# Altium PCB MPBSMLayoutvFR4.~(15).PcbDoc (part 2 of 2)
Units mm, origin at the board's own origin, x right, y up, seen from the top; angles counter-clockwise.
Board outline 131.7 x 110.39 mm, 4 copper layers (Top Layer, Power, GroundPlane, Bottom Layer), stack 2.286 mm thick; 156 components, 77 nets, 429 pads, 117 vias.
Unrouted connection lines stored in the file: 44.
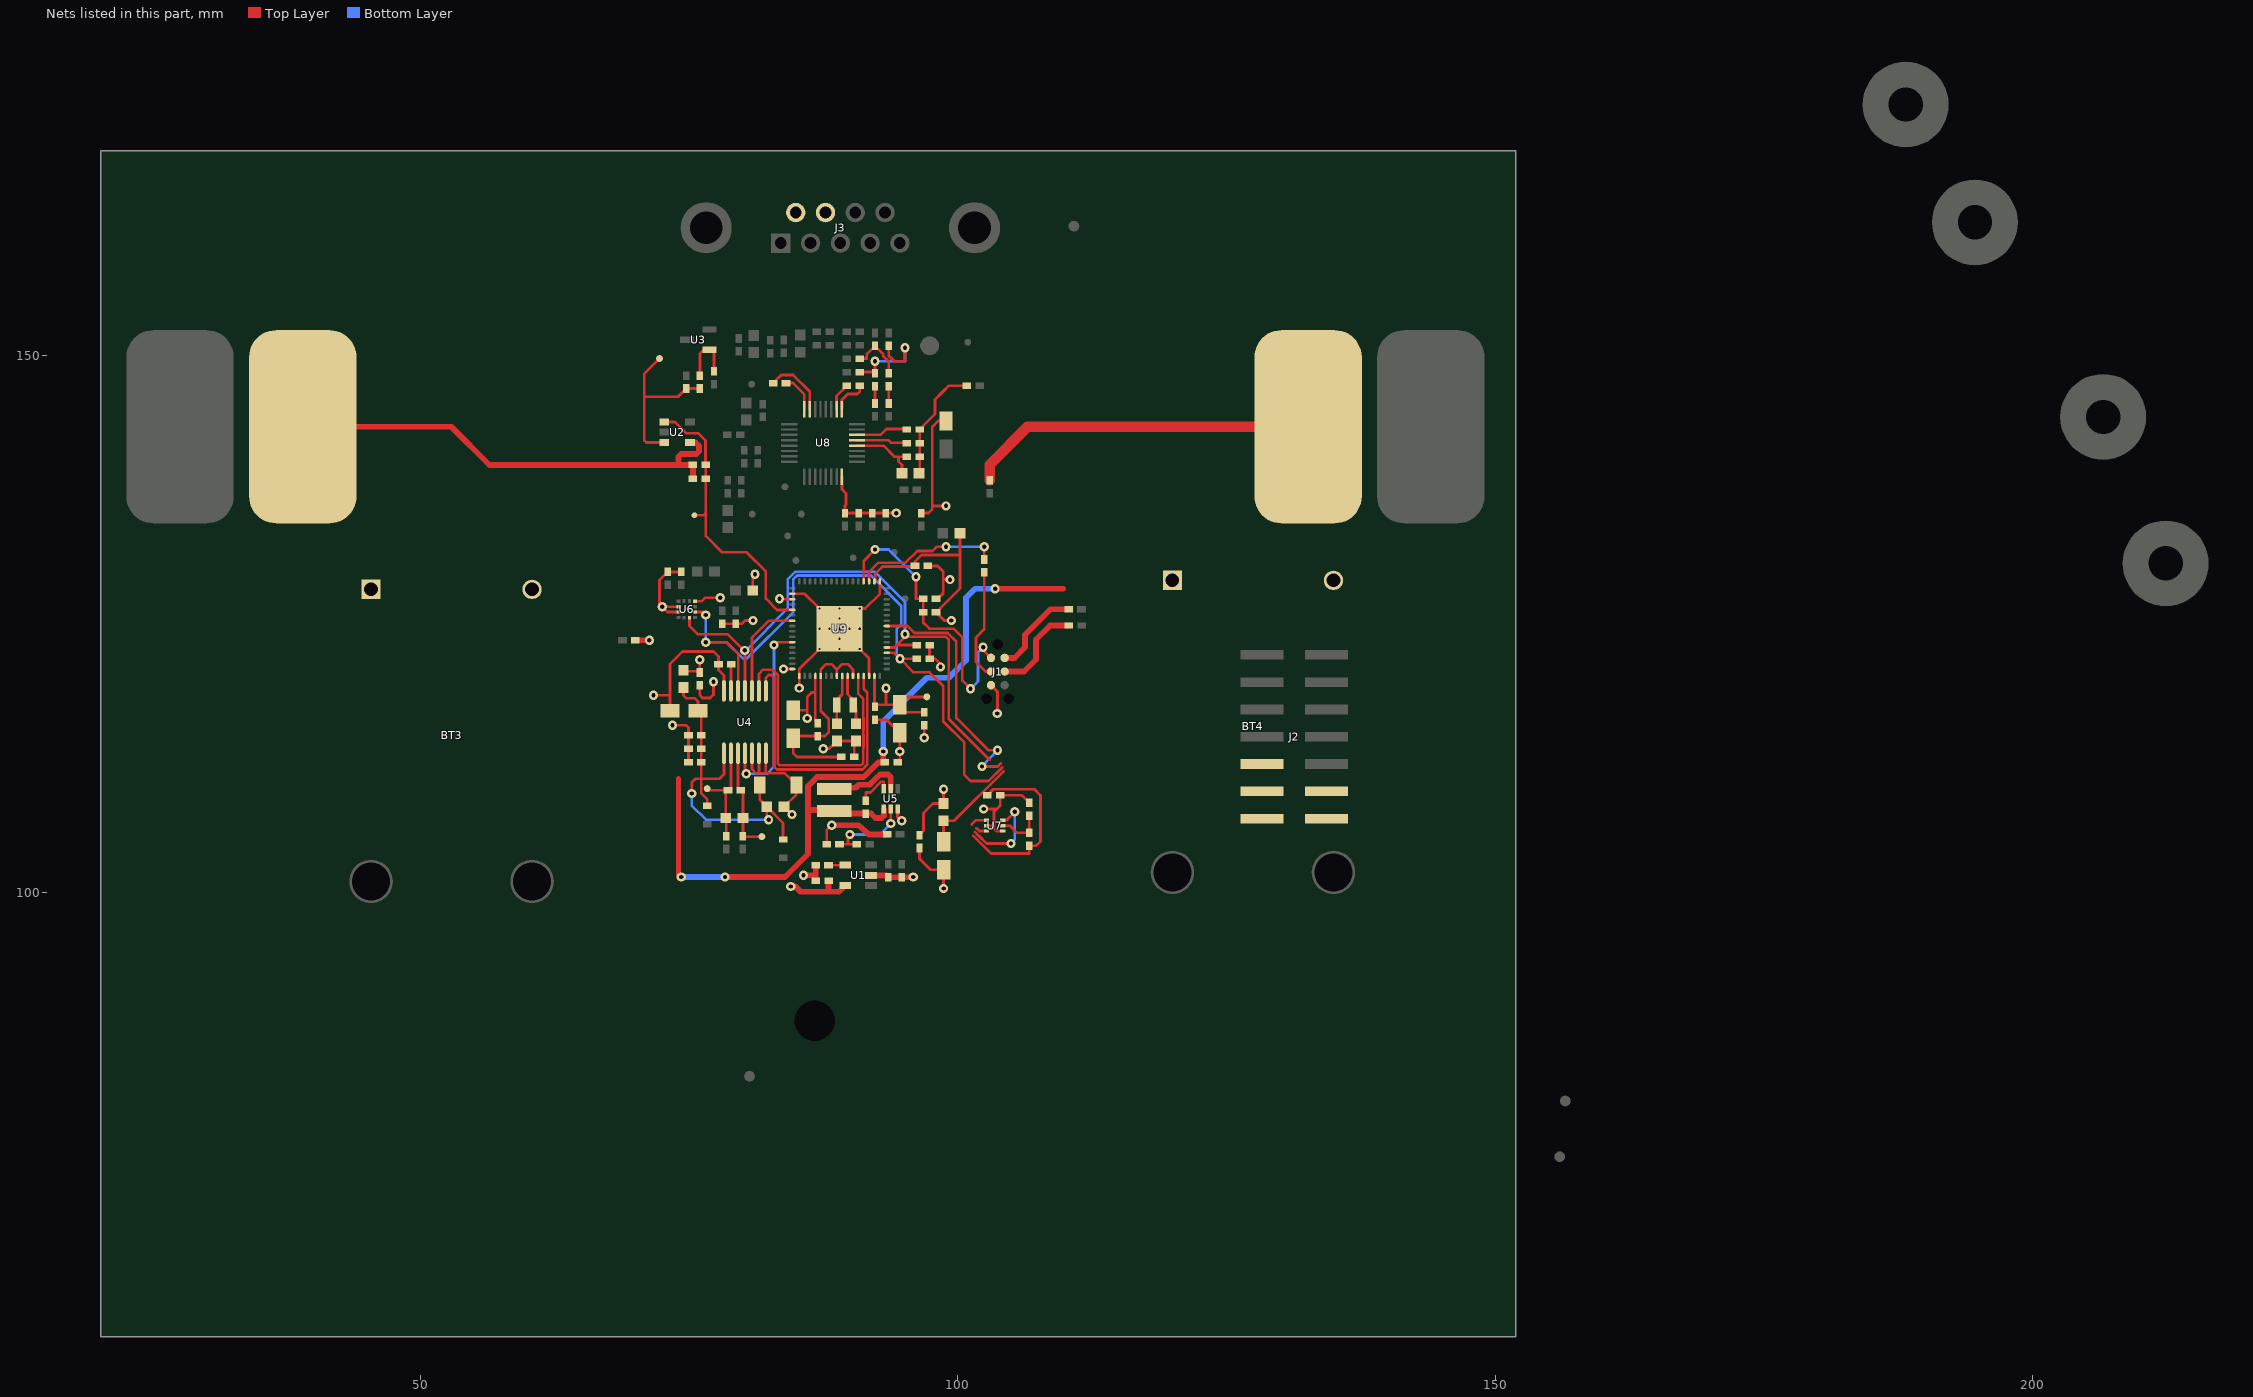
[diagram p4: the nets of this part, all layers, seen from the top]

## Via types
v1: diameter 0.864, hole 0.406, Top Layer to Bottom Layer, 104 vias
v2: diameter 0.5, hole 0.2, Top Layer to Bottom Layer, 13 vias

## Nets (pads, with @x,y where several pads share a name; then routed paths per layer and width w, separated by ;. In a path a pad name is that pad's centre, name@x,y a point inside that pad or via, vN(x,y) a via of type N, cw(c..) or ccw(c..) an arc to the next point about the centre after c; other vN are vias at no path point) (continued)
BOOST_INPUT: BT3.1 BT4.1 C34.1 L7.1 R16.1 U5.1 | length 73.3
  Top Layer w0.254: L7.1@88.494,107.681 L7.1@88.503,107.672 ; v1(93.04,113.132) v1@93.202,112.97
  Top Layer w0.5: 73.99,110.592 73.99,101.702 v1(74.244,101.448)
  Top Layer w0.54: v1(78.308,101.448) 83.896,101.448 86.03,103.581 86.03,109.906 86.868,110.744 91.211,110.744 92.583,112.116 C34.1@93.202,112.116 ; 86.03,107.696 L7.1@88.494,107.681 ; L7.1@88.714,107.35 R16.1@91.415,107.35 91.9,107.35 92.316,106.934 92.888,106.934 93.101,107.148 U5.1@93.101,107.762 ; C34.1@93.04,112.278 v1(93.04,113.132) ; v1(103.454,128.287) 109.803,128.287
  Bottom Layer w0.54: v1(74.244,101.448) v1(78.308,101.448) ; v1(93.04,113.132) 93.04,115.926 97.104,119.99 99.136,119.99 100.753,121.606 100.753,127.448 101.592,128.287 v1(103.454,128.287)
DVCC: 1.1 C1.1 C5.1 C6.1 C10.1 C14.1 C18.1 L1.1 L2.1 L3.1 L5.1 R1.1 R6.2 R31.1 R32.1 U1.5 U9.18 U9.35 U9.48 U9.63 | length 53
  Top Layer w0.254: L1.1@74.244,120.59 75.822,120.59 C10.1@75.846,120.613 ; C10.1@75.971,120.488 v1(75.971,121.666) ; L3.1@80.886,128.118 80.886,129.426 v1(81.102,129.642) ; v1@83.432,127.312 U9.35@84.576,127.312 ; v1(83.758,120.812) U9.48@84.576,120.812 ; U9.63@92.227,120.162 92.227,117.339 C6.1@92.278,117.288 ; U9.18@92.227,128.962 92.273,129.008 92.273,129.637 92.992,130.356 95.948,130.356 C18.1@95.996,130.404 95.996,130.82 96.596,131.42 100.152,131.42 ; C6.1@92.47,117.48 C1.1@94.564,117.48 ; 93.297,117.483 v1(93.297,119.027) ; C14.1@96.421,105.35 96.799,105.728 96.799,107.414 97.671,108.286 L2.1@98.661,108.286 v1(98.661,109.621) ; R1.1@96.85,116.78 95.264,116.78 C1.1@94.564,117.48 ; 1.1@97.104,118.212 95.296,118.212 C1.1@94.564,117.48 ; R32.1@97.358,123.038 R31.1@97.358,121.768 97.866,121.768 98.374,121.26 v1(98.374,121.006) ; v1(99.39,125.324) 98.72,125.324 R6.2@97.958,126.086 100.19,128.318 L5.1@100.19,133.452
  Top Layer w0.54: v1(84.43,100.559) v1@84.836,100.559 ; 84.861,100.584 85.369,100.076 87.955,100.076 ; C5.1@87.955,101.092 87.955,100.076 ; U1.5@89.503,100.65 88.929,100.076 87.955,100.076
  other v1: 83.388,127.356
EL_GSR1: C26.2 J3.7 R10.1 TP2.1 U2.4 | length 43.3
  Top Layer w0.254: U2.4@75.052,141.9 75.564,141.9
  Top Layer w0.54: TP2.1@39.014,143.358 52.832,143.358 56.388,139.802 R10.1@75.33,139.802 C26.2@75.33,138.532 ; 73.99,139.852 73.99,140.564 74.244,140.818 75.63,140.818 75.884,141.072 75.884,141.58 75.564,141.9
EL_GSR2: J3.6 R9.2 TP1.1 | length 32.6
  Top Layer w1: R9.2@102.946,138.37 102.946,139.827 106.477,143.358 TP1.1@132.588,143.358
GND: BT3.2 BT4.2 C1.2 C3.2 C4.2 C5.2 C6.2 C8.2 C9.2 C10.2 C11.2 C12.2 C13.2 C14.2 C15.2 C16.2 C17.2 C18.2 C19.2 C20.2 C21.2 C25.2 C27.2 C28.2 C29.1 C32.2 C33.2 C34.2 C35.2 C36.2 C37.2 C38.2 C41.2 C42.2 C58.2 C59.2 J1.6 J2.6 R2.1 R3.1 R17.1 U1.2 U4.5 U4.6 U4.7 U4.14 U5.3 U6.4 U6.8 U6.9 U7.2 U7.4 U8.24 U9.17 U9.34 U9.49 U9.62 U9.65 | length 145.9
  Top Layer w0.254: v1(71.653,118.364) 73.198,118.364 ; C9.2@73.198,116.942 73.198,118.364 ; v1(73.431,115.57) 74.701,115.57 74.914,115.357 C27.2@74.914,114.656 C11.2@74.914,113.386 C28.2@74.914,112.116 ; U6.9@73.977,126.111 72.949,126.111 v1(72.466,126.594) ; U6.8@73.977,126.611 72.483,126.611 v1(72.466,126.594) ; C37.2@74.244,129.847 C16.2@72.974,129.847 72.212,129.085 72.212,126.848 v1(72.466,126.594) ; U6.4@75.527,127.111 76.131,127.111 76.453,127.433 v1(77.873,127.433) ; C10.2@75.971,119.288 75.971,118.364 76.225,118.11 76.93,118.11 77.241,118.422 v1(77.241,119.634) ; C36.2@78.054,125.024 C17.2@79.324,125.024 79.88,125.024 80.18,125.324 v1(80.924,125.324) ; U4.14@78.219,118.764 78.219,120.193 77.708,120.704 C29.1@77.708,121.26 77.708,121.961 77.241,122.428 74.367,122.428 73.198,121.26 73.198,118.364 ; U4.5@80.819,112.964 80.819,111.484 81.204,111.1 82.118,111.1 ; 81.469,111.137 U4.6@81.469,112.964 ; U4.7@82.119,112.964 82.118,111.1 ; v1(84.553,107.266) 84.528,107.266 C33.2@83.803,107.991 84.957,109.145 C32.2@84.957,110.023 83.88,111.1 82.118,111.1 ; U9.34@84.576,127.812 85.726,127.812 v2(87.101,126.437) v2(88.976,124.562) ; v1(85.225,119.033) U9.49@85.225,120.162 85.225,120.811 v2(87.101,122.687) v2(88.976,124.562) ; v1(85.623,101.6) v1@85.636,101.613 ; v1(87.452,113.386) 87.998,113.386 88.722,114.11 C58.2@90.5,114.11 ; R17.1@87.776,104.496 87.776,105.812 v1(88.238,106.274) ; U8.24@89.202,138.704 89.202,137.544 89.584,137.162 89.584,136.099 89.484,135.999 C42.2@89.484,135.322 C41.2@90.754,135.322 C19.2@92.024,135.322 C20.2@93.294,135.322 v1@94.199,135.322 ; R2.1@90.338,112.624 C58.2@90.338,113.948 ; U9.62@91.727,120.162 91.727,121.811 v2(90.851,122.687) v2(88.976,124.562) ; C6.2@92.278,115.888 C6.2@92.278,116.088 93.356,116.088 C1.2@94.564,114.88 94.583,114.861 v1(94.583,113.132) 94.583,112.296 C34.2@94.402,112.116 C34.2@94.564,111.954 ; U9.17@92.727,128.962 92.727,127.805 91.359,126.437 v2(90.851,126.437) v2(88.976,124.562) ; C3.2@93.33,101.6 C3.2@93.502,101.428 ; v1(95.834,101.448) 95.834,101.194 v1@96.068,101.428 ; C14.2@96.421,104.15 96.421,103.147 97.446,102.122 C12.2@98.661,102.122 v1(98.661,100.374) ; C21.2@96.596,135.322 97.247,135.322 97.612,135.687 97.612,143.358 98.15,143.896 C15.2@98.882,143.896 C15.2@98.882,144.374 ; C18.2@97.196,130.404 98.12,130.404 98.628,129.896 98.628,129.134 ; 97.612,135.992 v1(98.882,135.992) ; C25.2@97.958,127.356 98.12,127.356 98.628,127.864 98.628,129.134 ; v1(99.263,129.134) 98.628,129.134 ; v1(102.383,107.783) 103.627,107.783 ; U7.2@102.661,106.221 103.331,106.221 ; J1.6@103.073,119.304 103.683,118.694 103.683,116.688 v1(103.657,116.662) ; U7.4@104.161,105.721 103.607,105.721 103.357,105.971 103.357,107.512 103.627,107.783 ; C38.2@106.639,108.352 105.923,109.068 C13.2@103.937,109.068 103.937,108.093 103.627,107.783
  Top Layer w0.354: U5.3@94.401,107.762 94.401,107.046 v1(94.767,106.68)
  Top Layer w0.54: R3.1@69.977,123.489 v1(71.279,123.489) ; v1@85.636,101.613 86.755,101.613 ; C5.2@86.755,101.092 86.755,101.613 ; C8.2@86.755,102.54 86.755,101.613 ; v1(88.238,106.274) 89.554,106.274 90.754,106.274 91.719,105.41 C35.2@93.455,105.41 ; U1.2@91.903,101.6 C3.2@93.33,101.6 ; C3.2@93.502,101.428 C4.2@94.772,101.428 v1@96.068,101.428
  other v1: 94.259,135.322
  other v2: 88.976,122.687 88.976,123.624 87.101,124.562 88.039,124.562 89.914,124.562 90.851,124.562 88.976,125.499 88.976,126.437
GSR_ANALOG_OUTPUT: 2.1 C26.1 R10.2 U2.1 U9.37 | length 26.9
  Top Layer w0.254: U2.1@72.652,143.8 73.659,143.8 74.71,142.748 75.828,142.748 76.488,142.088 76.488,140.14 76.53,140.098 R10.2@76.53,139.802 C26.1@76.53,138.532 76.53,135.23 ; 2.1@75.463,135.128 76.429,135.128 ; 76.429,135.23 76.53,135.23 ; U9.37@84.576,126.312 83.162,126.312 82.118,127.356 82.118,129.896 80.34,131.674 78.054,131.674 76.53,133.198 76.53,135.23
JTAG_TCK: J1.4 J2.4 R7.1 | length 10.4
  Top Layer w0.254: R7.1@102.438,129.804 102.438,124.511 101.676,123.749 101.676,121.463 102.565,120.574 J1.4@103.073,120.574
JTAG_TDO/TDI: C25.1 J1.2 J2.2 R6.1 U9.20 | length 28.1
  Top Layer w0.254: U9.20@91.227,128.962 91.227,130.876 v1(92.278,131.928) ; v1(96.088,129.388) 96.088,127.356 C25.1@96.758,127.356 R6.1@96.758,126.086 96.758,125.162 97.358,124.562 99.585,124.562 100.406,123.74 100.406,119.736 v1(101.168,118.974) ; v1(102.337,122.843) 102.337,122.58 J1.2@103.073,121.844
  Bottom Layer w0.254: v1(92.278,131.928) 93.548,131.928 v1(96.088,129.388) ; v1(101.168,118.974) 101.854,119.659 101.854,122.36 v1(102.337,122.843)
JTAG_TEST/SBWTCK: R7.2 U9.19 | length 13.7
  Top Layer w0.254: U9.19@91.727,128.962 91.727,129.852 92.584,130.71 95.124,130.71 96.215,131.801 97.611,131.801 97.992,132.182 v1(98.882,132.182) ; R7.2@102.438,131.004 v1(102.438,132.182)
  Bottom Layer w0.254: v1(98.882,132.182) v1(102.438,132.182)
JTAG_VCC_TARGET_IN: J1.3 J2.3 R5.1 | length 8.8
  Top Layer w0.54: J1.3@104.343,120.574 106.147,120.574 107.264,121.691 107.264,122.707 107.264,123.546 108.58,124.861 R5.1@110.316,124.861
JTAG_VCC_TOOL_OUT: J1.1 J2.1 R4.1 | length 8.5
  Top Layer w0.54: J1.1@104.343,121.844 105.258,121.844 106.248,122.834 106.248,124.003 108.61,126.365 R4.1@110.296,126.365
MSP_AVCC: C2.1 C7.1 R1.2 U9.52 | length 9.3
  Top Layer w0.254: C2.1@84.978,116.972 85.958,116.972 ; v1(85.958,116.21) 85.958,116.972 ; C7.1@86.726,115.982 86.726,118.618 ; U9.52@86.726,120.162 86.726,118.618 ; v1(96.85,114.402) R1.2@96.85,115.58 ; 85.958,116.972 85.958,118.191 86.385,118.618 86.726,118.618
MSP_AVSS: C2.2 C7.2 R2.2 U9.53 U9.56 U9.59 | length 20.5
  Top Layer w0.254: C2.2@84.658,114.372 84.658,112.979 85.014,112.624 R2.2@89.138,112.624 ; C2.2@84.85,114.564 C7.2@86.944,114.564 87.614,114.564 87.96,114.91 87.96,116.18 87.226,116.914 U9.53@87.226,120.162 87.226,120.779 87.706,121.26 88.214,121.26 88.718,120.756 ; U9.56@88.726,120.162 88.726,120.756 89.23,121.26 89.738,121.26 90.227,120.771 U9.59@90.227,120.162
MSP_LFXIN: C59.1 U9.57 Y1.1 | length 4.1
  Top Layer w0.254: C59.1@88.722,115.71 88.722,117.438 Y1.1@88.734,117.45 ; Y1.1@88.734,117.97 89.226,118.462 U9.57@89.226,120.162
MSP_LFXOUT: C58.1 U9.58 Y1.2 | length 4.3
  Top Layer w0.254: U9.58@89.726,120.162 89.726,118.477 Y1.2@90.234,117.97 ; Y1.2@90.234,117.45 90.5,117.184 C58.1@90.5,115.71
MSP_P1.0_INT: U4.10 U9.39 | length 9.4
  Top Layer w0.254: U4.10@80.819,118.764 80.819,123.749 ; 80.835,123.749 82.398,125.312 U9.39@84.576,125.312
MSP_P2.7_INT: U7.3 U9.9 | length 24.2
  Top Layer w0.254: U9.9@93.376,124.812 95.3,124.812 95.958,124.154 99.036,124.154 99.844,123.346 99.844,116.234 102.819,113.259 v1(103.683,113.259) ; 101.723,105.989 101.992,105.721 U7.3@102.661,105.721 ; v1@102.243,111.743 103.704,111.743 103.972,112.011
  Bottom Layer w0.254: v1(102.235,111.735) v1(103.683,113.259)
MSP_P4.0_INT: U4.9 U9.60 | length 28.4
  Top Layer w0.254: U4.9@81.469,118.764 81.469,120.356 81.864,120.752 82.731,120.752 83.234,120.248 83.234,112.016 83.388,111.862 91.008,111.862 91.193,112.046 91.193,113.506 91.202,113.516 91.202,114.704 91.193,114.713 91.193,115.106 91.202,115.116 91.202,116.304 91.193,116.313 91.193,118.027 90.727,118.493 U9.60@90.727,120.162
MSP_P4.1_INT: U4.8 U9.61 | length 27.8
  Top Layer w0.254: U4.8@82.119,118.764 82.119,119.99 82.372,120.244 82.626,120.244 82.88,119.99 82.88,111.718 83.144,111.454 91.108,111.454 ; 91.108,111.461 91.547,111.9 91.547,113.36 91.556,113.369 91.556,118.612 91.227,118.942 U9.61@91.227,120.162
MSP_P9.3_OUT: U4.4 U9.43 | length 18
  Top Layer w0.254: U4.4@80.169,112.964 80.169,111.169 v1(80.289,111.049) ; v1(82.88,123.038) 83.154,123.312 U9.43@84.576,123.312
  Bottom Layer w0.254: v1(80.289,111.049) 82.211,111.049 82.88,111.718 v1(82.88,123.038)
MSP_UCB0SCL_TMP103_SCL_RF430CL330HCPW_SCL: R32.2 U4.11 U6.12 U7.1 U9.5 | length 56.8
  Top Layer w0.254: U6.12@75.002,125.586 75.002,124.82 75.768,124.054 78.562,124.054 v1@80.118,122.497 ; U4.11@80.169,118.764 v1@80.169,122.447 ; U9.5@93.376,122.812 94.084,122.812 94.31,123.038 ; v1(95.072,124.054) v1@95.072,123.8 ; R32.2@95.996,123.038 94.31,123.038 ; 101.273,106.343 101.651,106.721 U7.1@102.661,106.721 ; 102.926,112.365 102.744,112.547 99.136,116.18 99.136,123.546 98.882,123.8 v1@95.072,123.8 ; 94.31,123.038 v1@95.072,123.8
  Bottom Layer w0.254: v1(80.16,122.539) 80.169,122.531 80.169,122.447 84.15,126.428 84.15,129.134 84.883,129.866 92.248,129.866 95.072,127.042 v1(95.072,124.054)
MSP_UCB0SDA_TMP103_SDA_RF430CL330HCPW_SDA: R31.2 U4.12 U6.2 U7.6 U9.4 | length 70.6
  Top Layer w0.254: U6.2@75.527,126.111 76.251,126.111 v1(76.53,125.832) ; v1(76.53,123.292) 78.476,123.292 79.535,122.233 79.535,118.78 U4.12@79.519,118.764 ; U9.4@93.376,122.312 94.056,122.312 v1(94.6,121.768) ; R31.2@96.158,121.768 v1(94.6,121.768) ; 101.577,105.635 101.88,105.332 101.887,105.332 102.649,104.57 v1(104.935,104.57) ; 104.119,111.657 102.85,110.388 101.168,110.388 100.597,110.96 100.597,113.957 98.628,115.926 98.628,119.228 97.358,120.498 95.87,120.498 v1(94.6,121.768) ; U7.6@104.161,106.721 104.496,106.721 v1(105.291,107.516)
  Bottom Layer w0.254: v1(76.53,125.832) v1(76.53,123.292) 78.476,123.292 80,121.768 80.34,121.768 84.658,126.086 84.658,129.134 85.037,129.512 91.9,129.512 94.718,126.694 94.718,124.97 94.31,124.562 94.31,122.058 v1(94.6,121.768) ; v1(104.935,104.57) 105.291,104.925 v1(105.291,107.516)
Net3_1: 3.1 R11.1 R12.2 U2.3 | length 15.6
  Top Layer w0.254: 70.804,146.152 73.941,146.152 R12.2@74.707,146.917 R11.1@75.977,146.917 ; 3.1@72.212,149.708 70.804,148.3 70.804,142.088 70.992,141.9 U2.3@72.652,141.9
Net4_1: 4.1 C30.1 C31.1 R13.1 U4.2 | length 9.9
  Top Layer w0.254: 4.1@76.653,109.676 76.814,109.515 C31.1@78.593,109.515 ; R13.1@78.431,105.255 78.431,106.903 C30.1@78.393,106.941 78.393,109.315 C31.1@78.593,109.515 ; U4.2@78.869,112.964 78.869,109.791 C31.1@78.593,109.515
Net5_1: 5.1 C30.2 C31.2 R14.1 U4.3 | length 9.9
  Top Layer w0.254: U4.3@79.519,112.964 79.519,109.788 C31.2@79.793,109.515 79.993,109.315 C30.2@79.993,106.941 79.993,105.293 80.089,105.197 5.1@81.987,105.197
NetC8_1: C8.1 U1.4 | length 1.6
  Top Layer w0.254: C8.1@87.951,102.54 87.961,102.55 U1.4@89.503,102.55
NetC29_2: C29.2 U4.13 | length 2.5
  Top Layer w0.254: U4.13@78.869,118.764 78.869,121.22 C29.2@78.908,121.26
NetC38_1: C38.1 R18.1 U7.5 | length 4.3
  Top Layer w0.254: U7.5@104.161,106.221 104.834,106.221 105.497,105.558 R18.1@106.639,105.558 C38.1@106.639,107.152
NetC43_1: C43.1 R19.2 R20.2 R21.2 R22.1 | length 10.9
  Top Layer w0.254: C43.1@96.434,139.094 R20.2@96.434,140.564 R21.2@96.434,141.834 96.434,141.876 R19.2@96.434,143.104 97.866,144.536 97.866,145.898 98.586,146.618 99.136,147.168 R22.1@100.822,147.168
NetC43_2: C43.2 R20.1 U8.28 | length 6.7
  Top Layer w0.254: U8.28@90.602,141.603 93.055,141.603 94.094,140.564 94.463,140.564 ; C43.2@94.78,139.04 94.78,139.818 94.463,140.135 94.463,140.564 ; R20.1@95.234,140.564 94.463,140.564
NetC45_1: C45.1 U8.2 | length 2.6
  Top Layer w0.254: U8.2@88.702,145.003 88.702,146.224 C45.1@89.646,147.168
NetC45_2: C45.2 U8.1 | length 3.4
  Top Layer w0.254: U8.1@89.202,145.003 89.202,145.87 89.738,146.406 90.64,146.406 90.846,146.612 C45.2@90.846,147.168
NetC46_2: C46.2 C48.2 C49.2 | length 10.4
  Top Layer w0.254: C46.2@90.846,148.45 C49.2@92.149,148.45 ; C49.2@92.278,148.322 v1(92.278,149.454) ; C48.2@93.548,150.886 93.554,150.88 93.554,149.967 94.068,149.454 95.072,149.454 v1(95.072,150.724)
  Bottom Layer w0.254: v1(92.278,149.454) 95.072,149.454 v1(95.072,150.724)
NetC47_1: C47.1 U8.8 | length 3.5
  Top Layer w0.254: C47.1@83.988,147.422 84.658,147.422 85.702,146.378 U8.8@85.702,145.003
NetC47_2: C47.2 U8.7 | length 6
  Top Layer w0.254: C47.2@82.788,147.422 83.55,148.184 84.658,148.184 86.202,146.64 U8.7@86.202,145.003
NetC49_1: C49.1 R26.1 | length 1.6
  Top Layer w0.254: R26.1@92.278,145.528 C49.1@92.278,147.122
NetC52_2: C52.2 C53.2 C54.2 | length 5.3
  Top Layer w0.254: C54.2@90.846,149.708 91.516,149.708 91.516,150.124 C52.2@92.278,150.886 93.04,150.124 93.04,149.962 93.548,149.454 C53.2@93.548,148.322
NetC53_1: C53.1 R27.1 | length 1.6
  Top Layer w0.254: R27.1@93.548,145.528 C53.1@93.548,147.122
NetL7_2: L7.2 U5.5 | length 5.5
  Top Layer w0.254: 91.821,110.033 91.821,110.084
  Top Layer w0.54: L7.2@89.941,109.752 90.473,109.752 90.754,110.033 91.821,110.033 ; 91.821,110.084 92.401,110.664 92.735,110.998 93.497,110.998 93.751,110.744 U5.5@93.751,109.662
NetR8_1: R8.1 R11.2 U3.1 | length 5.5
  Top Layer w0.254: R11.2@75.977,148.117 75.977,150.17 76.342,150.536 77.292,150.536 R8.1@77.292,148.53
NetR15_1: R15.1 R17.2 U5.2 | length 8.1
  Top Layer w0.254: R17.2@88.976,104.496 89.773,104.496 ; v1(89.941,105.41) 89.773,105.242 89.773,104.496 ; R15.1@90.57,104.496 89.773,104.496 ; v1(93.751,106.426) U5.2@93.751,107.762
  Bottom Layer w0.254: v1(89.941,105.41) 92.735,105.41 v1(93.751,106.426)
NetR16_2: R16.2 U5.6 | length 3.5
  Top Layer w0.254: R16.2@91.415,108.55 91.415,109.271 91.465,109.322 91.846,109.322 92.851,110.327 93.091,110.327 93.091,109.672 U5.6@93.101,109.662
NetR19_1: R19.1 U8.30 | length 4.9
  Top Layer w0.254: U8.30@90.602,142.603 92.794,142.603 93.336,143.146 R19.1@95.234,143.146
NetR21_1: R21.1 U8.29 | length 4.7
  Top Layer w0.254: U8.29@90.602,142.103 93.533,142.103 93.76,141.876 R21.1@95.234,141.876
RF430_DVCC: C9.1 C11.1 C27.1 C28.1 C32.1 C33.1 D1.1 D2.1 L1.2 U4.1 | length 34
  Top Layer w0.254: 74.447,118.512 74.447,118.338 74.694,118.092 75.482,118.092 75.798,117.775 C9.1@75.798,116.942 C9.1@76.022,117.166 ; v1(75.209,109.22) 75.209,110.236 75.565,110.592 76.108,110.592 ; C28.1@76.114,112.116 C11.1@76.114,113.386 C27.1@76.114,114.656 C9.1@76.114,116.626 ; C28.1@76.206,112.024 76.108,111.926 76.108,110.592 ; D1.1@76.653,108.079 76.653,108.691 76.108,109.235 76.108,110.592 ; U4.1@78.219,112.964 78.219,111.01 77.8,110.592 76.108,110.592 ; C32.1@81.557,110.023 81.557,108.637 C33.1@82.203,107.991 ; v1(82.372,106.782) 82.203,106.951 C33.1@82.203,107.991 ; D2.1@83.718,104.989 83.718,106.475 C33.1@82.203,107.991
  Bottom Layer w0.254: v1(75.209,109.22) 75.209,108.102 76.53,106.782 v1(82.372,106.782)
TMP_DVCC: C12.1 C13.1 L2.2 R18.2 | length 27
  Top Layer w0.254: C12.1@98.661,104.722 L2.2@98.661,106.686 99.648,106.686 104.265,111.303 ; 101.43,105.281 103.081,103.63 106.639,103.63 R18.2@106.639,104.358 107.263,104.358 107.674,104.768 107.674,109.049 107.105,109.618 103.287,109.618 C13.1@102.737,109.068
pads on no net: BT3.3 BT3.4 BT4.3 BT4.4 FID1.1 FID2.1 FID3.1 H1.0 H2.0 H3.0 H4.0 H5.1 H6.1 H7.1 H8.1 H9.0 H10.0 H11.0 H12.0 J1.5 J1.MH1 J1.MH2 J1.MH3 J2.5 J2.7 J2.8 J2.9 J2.10 J2.11 J2.12 J2.13 J2.14 J3.3 J3.5 J3.8 J3.9 U3.3 U6.10 U8.17 U9.1 U9.2 U9.3 U9.6 U9.7 U9.8 U9.10 U9.11 U9.12 U9.13 U9.15 U9.21 U9.22 U9.23 U9.24 U9.36 U9.40 U9.41 U9.42 U9.44 U9.45 U9.46 U9.47 U9.50 U9.51 U9.54 U9.55 U9.64
copper on no net: | length 0.5
  Top Layer w0.254: 103.403,124.206 v1(103.403,124.714)

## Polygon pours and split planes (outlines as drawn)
DVCC on Power (split plane): 101.293,142.288 101.293,131.727 100.657,131.092 77.549,131.092 76.914,131.727 76.914,133.144 78.108,134.338 92.024,134.338 92.074,134.348 92.116,134.376 97.196,139.456 97.224,139.498 97.234,139.548 97.234,142.796 97.642,143.205 100.376,143.205
DVCC on Power (split plane): 86.469,117.065 86.815,116.61 86.815,112.624 86.825,112.574 86.853,112.532 86.895,112.504 86.944,112.494 94.91,112.494 94.96,112.504 95.002,112.532 95.926,113.456 95.954,113.498 95.964,113.548 95.964,115.796 97.727,115.796 97.727,115.57 97.727,113.937 97.267,113.477 95.989,112.2 95.527,111.737 85.686,111.737 85.042,112.41 85.042,116.653 85.456,117.089
DVCC on Power (split plane): 89.609,154.534 89.567,146.998 80.849,147.043 80.848,147.043 80.824,147.038 80.799,147.033 80.778,147.019 80.757,147.006 80.757,147.005 80.743,146.984 80.729,146.964 80.729,146.963 80.724,146.939 80.719,146.914 80.719,143.104 80.729,143.054 80.757,143.012 80.799,142.984 80.848,142.974 85.545,142.974 85.545,141.201 82.372,141.201 82.323,141.191 82.281,141.163 82.253,141.121 82.243,141.072 82.243,135.359 76.101,135.359 76.101,139.09 76.091,139.14 76.063,139.182 73.866,141.379 73.866,145.59 76.883,148.607 78.021,148.607 78.046,148.612 78.07,148.616 78.071,148.617 78.092,148.631 78.112,148.644 78.113,148.645 78.127,148.665 78.141,148.686 78.141,148.687 78.146,148.711 78.151,148.736 78.183,154.658 89.609,154.658
DVCC on Power (split plane): 151.407,158.471 151.407,59.159 20.729,59.159 20.729,168.527 151.407,168.527
ADS_AVSS on GroundPlane (split plane): 151.407,158.471 151.407,59.159 20.729,59.159 20.729,127.759 76.632,127.734 76.681,127.744 76.724,127.772 76.727,127.776 76.742,127.784 88.378,136.269 95.146,136.269 95.146,135.636 95.156,135.586 95.184,135.544 95.226,135.516 95.275,135.507 97.866,135.507 97.916,135.516 97.958,135.544 97.986,135.586 97.996,135.636 97.996,136.878 100.785,136.878 100.785,128.676 100.795,128.627 100.823,128.585 100.865,128.557 100.914,128.547 150.673,128.547 150.722,128.557 150.764,128.585 150.792,128.627 150.802,128.676 150.792,128.726 150.764,128.768 150.722,128.796 150.673,128.806 101.044,128.806 101.044,137.008 101.034,137.057 101.006,137.099 100.964,137.127 100.914,137.137 97.866,137.137 97.817,137.127 97.775,137.099 97.747,137.057 97.737,137.008 97.737,135.765 95.405,135.765 95.405,136.398 95.395,136.448 95.367,136.49 95.325,136.518 95.275,136.527 88.336,136.527 88.321,136.524 88.306,136.524 88.297,136.52 88.287,136.518 88.274,136.509 88.26,136.503 76.59,127.993 20.729,128.018 20.729,168.527 151.407,168.527

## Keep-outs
Keep-Out Layer:
  text ".Layer_Name" at 157.226,108.306 h1.52

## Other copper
Top Layer:
  text ".Layer_Name" at 157.226,156.566 h1.52
Bottom Layer:
  text ".Layer_Name" at 157.226,154.026 h1.52
  text "SVN:" at 48.603,114.91 h1.52 r90
  text ".VersionControl_RevNumber" at 48.603,107.823 h1.52 r90
  text "UL94V-0" at 54.635,69.774 h1.52 r90
Power (plane layer: these items are gaps in the copper):
  rectangle: 73.736,69.952 99.136,99.67
  lines w0.254: 97.856,115.57 97.856,115.926 ; 97.856,115.926 97.453,115.926 95.834,115.926 95.834,113.548 94.91,112.624 87.164,112.624 86.944,112.624 86.944,116.654 86.534,117.193 85.402,117.219 84.912,116.705 84.912,112.358 85.63,111.608 91.098,111.608 95.58,111.608 96.081,112.108 97.358,113.386 97.856,113.884 97.856,115.926 ; 73.736,141.326 75.971,139.09 75.971,135.23 80.144,135.23 82.372,135.23 82.372,141.072 85.674,141.072 85.674,143.104 80.848,143.104 80.848,146.914 89.696,146.868 89.738,154.534 89.738,154.788 78.054,154.788 78.021,148.736 76.829,148.736 73.736,145.644 73.736,141.326 ; 76.784,131.674 76.784,133.198 78.054,134.468 92.024,134.468 97.104,139.548 97.104,142.85 97.589,143.334 100.43,143.334 101.422,142.342 101.422,131.674 100.711,130.962 77.495,130.962 76.784,131.674
GroundPlane (plane layer: these items are gaps in the copper):
  rectangle: 73.736,69.952 99.136,99.67
  lines w0.254: 18.999,127.889 76.632,127.864 ; 76.666,127.888 88.336,136.398 95.275,136.398 95.275,135.636 97.866,135.636 97.866,137.008 100.914,137.008 100.914,128.676 150.673,128.676

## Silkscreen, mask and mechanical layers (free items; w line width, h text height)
Top Overlay:
  region: 95.275,77.724 95.275,85.344 92.735,85.344 92.735,77.724
  lines w1: 72.822,70.891 99.949,70.891 99.949,98.222 72.822,98.222 72.822,70.891
  lines w2: 19.888,133.325 43.688,133.325 149.2,133.325 ; 47.879,60.96 47.879,132.918 47.879,167.716 ; 124.587,61.646 124.587,167.157
  text "GSR" at 129.007,153.289 h4
  text "ECG" at 140.386,153.238 h4
  text "ECG" at 23.647,152.806 h4
  text "GSR" at 36.297,152.756 h4
  text "GND" at 45.542,131.318 h1.02
  text "VCC" at 59.055,129.845 h1.02
  text ".Layer_Name" at 157.226,128.626 h1.52
  text "JTAG" at 105.689,126.009 h1.02
  text "BAT" at 109.499,122.987 h1.02
  text "VCC" at 60.935,121.361 h1.02
  text "GND" at 45.796,121.158 h1.02
  text "FOR DEMO PURPOSES ONLY" at 75.438,94.259 h1.02
  text "MPBSM" at 79.019,91.44 h1.02
  text "REV A" at 79.019,89.916 h1.02
  text "TI" at 91.11,87.884 h1.52
  text "©" at 93.751,87.63 h2.67
  text ".CopyrightYear" at 84.099,77.724 h1.52
  text "MADE IN U.S." at 77.749,75.438 h1.52
  text "NFC Antenna" at 79.502,68.504 h2
  text "-" at 49.86,67.666 h1.52 r90
  text "Place phone here" at 51.867,62.84 h10
Bottom Overlay:
  text ".Layer_Name" at 157.226,126.086 h1.52
Top Paste:
  text ".Layer_Name" at 157.226,123.546 h1.52
Bottom Paste:
  text ".Layer_Name" at 157.226,121.006 h1.52
Top Solder:
  text ".Layer_Name" at 157.226,118.466 h1.52
  text ".Layer_Name" at 157.226,115.926 h1.52
Bottom Solder:
  text ".Layer_Name" at 157.226,113.386 h1.52
Drill Guide:
  text ".Layer_Name" at 157.226,110.846 h1.52
M1 Board Outline:
  lines w0.254: 74.244,58.257 100.533,58.257
  text ".Layer_Name" at 157.226,151.486 h1.52
M2 Board Dimensions:
  rectangle: 17.577,32.982 20.752,36.157
  rectangle: 20.752,29.807 30.277,32.982
  lines w0.178: 17.577,32.982 42.977,32.982 ; 20.752,29.807 20.752,36.157 ; 23.927,29.807 23.927,36.157 ; 30.277,29.807 30.277,36.157 ; 36.627,29.807 36.627,36.157 ; 17.577,29.807 42.977,29.807 42.977,36.157 17.577,36.157 17.577,29.807
  text ".Layer_Name" at 18.034,37.338 h1.52
M3 3D STEP Top:
  text ".Layer_Name" at 157.226,148.946 h1.52
M4 3D STEP Bottom:
  text ".Layer_Name" at 157.226,146.406 h1.52
M5 Assembly Top:
  lines w0.254: 10.16,16.607 177.8,16.607 ; 10.16,21.772 177.851,21.772 ; 10.16,26.937 10.16,11.443 111.887,11.443 177.851,11.443 177.851,26.937 10.173,26.937 10.173,11.443 50.19,11.443 ; 72.771,11.443 72.771,26.937 ; 104.953,21.772 104.953,26.937 ; 126.289,21.772 126.289,26.937 ; 142.088,11.278 142.088,16.43
  text "COMPONENTS MARKED 'DNP' SHOULD NOT BE POPULATED." at 46.876,32.144 h1.52
  text "ASSEMBLY VARIANT:" at 46.863,29.21 h1.52
  text ".VariantName" at 73.177,29.21 h1.52
  text "PCB VIEWED FROM TOP SIDE" at 11.773,23.58 h1.52
  text "BOARD #:" at 74.676,23.58 h1.52
  text ".PRJ_Number" at 88.532,23.58 h1.52
  text "REV:" at 109.982,23.58 h1.52
  text ".PCB_Rev" at 117.386,23.58 h1.52
  text "SVN REV:" at 131.267,23.58 h1.52
  text ".VersionControl_RevNumber" at 144.12,23.58 h1.52
  text "IGNORE ->" at 11.773,18.428 h1.52
  text "PLOT NAME =" at 11.773,13.199 h1.52
  text ".plot_File_Name" at 32.233,13.199 h1.52
  text "GENERATED    :" at 74.727,13.199 h1.52
  text ".Print_Date" at 96.812,13.199 h1.52
  text ".Print_Time" at 115.329,13.199 h1.52
  text "TEXAS INSTRUMENTS" at 147.447,13.199 h1.52
M6 Assembly Bottom:
  lines w0.254: 10.147,21.759 177.838,21.759 ; 10.198,16.595 177.838,16.595 ; 45.91,11.265 45.91,16.417 ; 61.709,21.759 61.709,26.924 ; 83.045,21.759 83.045,26.924 ; 115.227,11.43 115.227,26.924 ; 137.808,11.43 177.825,11.43 177.825,26.924 10.147,26.924 10.147,11.43 76.111,11.43 177.838,11.43 177.838,26.924
  text "COMPONENTS MARKED 'DNP' SHOULD NOT BE POPULATED." at 172.568,32.156 h1.52
  text ".VariantName" at 146.05,29.21 h1.52
  text "ASSEMBLY VARIANT:" at 172.441,29.21 h1.52
  text ".VersionControl_RevNumber" at 43.878,23.567 h1.52
  text "SVN REV:" at 56.731,23.567 h1.52
  text ".PCB_Rev" at 70.612,23.567 h1.52
  text "REV:" at 78.016,23.567 h1.52
  text ".PRJ_Number" at 99.466,23.567 h1.52
  text "BOARD #:" at 113.322,23.567 h1.52
  text "PCB VIEWED FROM BOTTOM SIDE" at 176.225,23.567 h1.52
  text "IGNORE ->" at 82.292,18.428 h1.52
  text "TEXAS INSTRUMENTS" at 40.551,13.187 h1.52
  text ".Print_Time" at 72.669,13.187 h1.52
  text ".Print_Date" at 91.186,13.187 h1.52
  text "GENERATED    :" at 113.271,13.187 h1.52
  text ".plot_File_Name" at 155.766,13.187 h1.52
  text "PLOT NAME =" at 176.225,13.187 h1.52
M9 Title Sheet:
  drawing of 57 lines, arcs and shapes, not listed
  text "1" at 36.369,243.091 h1.78
  text "2" at 99.758,243.091 h1.78
  text "3" at 162.988,243.091 h1.78
  text "4" at 226.657,243.091 h1.78
  text "5" at 290.131,243.091 h1.78
  text "6" at 353.758,243.091 h1.78
  text "A" at 6.998,214.058 h1.78
  text "A" at 382.918,214.058 h1.78
  text "B" at 6.998,153.606 h1.78
  text "B" at 382.918,153.606 h1.78
  text ".Layer_Name" at 157.226,143.866 h1.52
  text "C" at 6.998,93.281 h1.78
  text "C" at 382.918,93.281 h1.78
  text "PROJECT TITLE:" at 305.702,46.012 h1.14
  text ".PRJ_Title" at 306.972,42.626 h1.78
  text "DESIGNED FOR:" at 305.702,38.367 h1.14
  text ".PRJ_Customer" at 306.972,34.811 h1.78
  text "D" at 6.998,33.084 h1.78
  text "D" at 382.918,33.084 h1.78
  text "FILE NAME:" at 305.702,30.747 h1.14
  text ".PCB_File_Name_No_Path" at 306.972,27.699 h1.78
  text "Texas Instruments (TI) and/or its licensors do not warrant the accuracy or completeness of this specification" at 179.476,23.588 h1.14
  text "ENGINEER:" at 305.702,23.381 h1.14
  text "LAYOUT BY:" at 343.929,23.381 h1.14
  text "or any information contained therein. TI and/or its licensors do not warrant that this design will meet" at 178.334,20.726 h1.14
  text ".PRJ_Engineer" at 306.972,19.444 h1.78
  text ".PCB_Layout" at 345.211,19.444 h1.78
  text "the specifications, will be suitable for your application or fit for any particular purpose, or will operate in" at 178.334,17.865 h1.14
  text "ALTIUM DESIGNER VERSION:" at 343.929,15.507 h1.14
  text "an implementation. TI and/or its licensors do not warrant that the design is production worthy. You should" at 178.334,15.003 h1.14
  text "completely validate and test your design implementation to confirm the system functionality for your application." at 179.476,12.141 h1.14
  text ".print_Scale" at 306.972,12.12 h1.78
  text ".Application_BuildNumber" at 345.211,12.12 h1.78
  text "1" at 36.369,6.871 h1.78
  text "2" at 99.758,6.871 h1.78
  text "3" at 162.988,6.871 h1.78
  text "4" at 226.657,6.871 h1.78
  text "5" at 290.131,6.871 h1.78
  text "6" at 353.758,6.871 h1.78
M10 Fab Notes:
  drawing of 185 lines, arcs and shapes, not listed
  text "DESIGN INFORMATION" at 332.055,190.348 h1.52
  text "MIN. TRACK WIDTH:" at 315.683,185.776 h1.52
  text "8" at 343.527,185.776 h1.52
  text "MIL" at 347.458,185.776 h1.52
  text "MIN. CLEARANCE:" at 315.683,182.423 h1.52
  text "0.2" at 342.003,182.423 h1.52
  text "mm" at 347.458,182.423 h1.52
  text "MIN. VIA PAD SIZE:" at 315.683,179.07 h1.52
  text "24" at 342.766,179.07 h1.52
  text "MIL" at 347.458,179.07 h1.52
  text "0.05mm (2MIL)" at 333.336,175.471 h1.52
  text "MINIMUM ANNULAR RING" at 307.32,175.362 h1.52
  text "EXTERNAL" at 351.319,175.362 h1.52
  text "PER" at 312.4,172.364 h1.52
  text "IPC-D-275 CLASS 2 LEVEL C" at 317.988,172.364 h1.52
  text "MIL, HOLES" at 355.789,169.512 h1.52
  text "+/-" at 345.821,169.494 h1.52
  text "+/-" at 367.513,169.494 h1.52
  text "REGISTRATION TOLERANCES:" at 307.32,169.367 h1.52
  text "METAL" at 337.795,169.367 h1.52
  text "5" at 352.43,169.367 h1.52
  text "3" at 373.588,169.367 h1.52
  text "MIL" at 376.541,169.367 h1.52
  text "MATERIAL:" at 305.421,164.047 h1.52
  text "FR-4 High Tg" at 330.477,160.482 h1.52
  text "FR-408" at 316.115,160.265 h1.52
  text "X" at 326.579,160.265 h1.52
  text "OTHER" at 353.91,160.265 h1.52
  text "62 MIL (1.6mm) +/-10%" at 324.245,156.132 h1.52
  text "THICKNESS:" at 307.32,156.023 h1.52
  text "X" at 320.99,156.023 h1.52
  text "OTHER" at 356.882,156.023 h1.52
  text "TOLERANCE:" at 307.32,152.01 h1.52
  text "X" at 328.639,152.01 h1.52
  text "ANSI IPC-6012 TYPE 3 CLASS 2" at 333.387,152.01 h1.52
  text "OTHER +/-" at 333.387,148.047 h1.52
  text "BOW & TWIST:" at 307.32,144.06 h1.52
  text "X" at 328.639,144.06 h1.52
  text "ANSI IPC-6012 TYPE 3 CLASS 2" at 333.387,144.06 h1.52
  text ".Layer_Name" at 157.226,141.326 h1.52
  text "OTHER +/-" at 333.387,140.034 h1.52
  text "DRILLING:" at 305.421,136.516 h1.52
  text "REFERENCE:" at 307.32,133.544 h1.52
  text "X" at 323.785,133.544 h1.52
  text "AS SHOWN" at 328.535,133.544 h1.52
  text "X" at 346.671,133.544 h1.52
  text "NC_DRILL FILES" at 350.151,133.544 h1.52
  text "PTH MIN COPPER THICKNESS:" at 307.32,129.531 h1.52
  text "X" at 341.616,129.531 h1.52
  text "1MIL" at 345.096,129.531 h1.52
  text "OTHER" at 357.72,129.531 h1.52
  text "BOARD FINISH:" at 305.421,125.492 h1.52
  text "SILKSCREEN:" at 309.364,122.495 h1.52
  text "X" at 333.463,122.495 h1.52
  text "TOP" at 336.663,122.495 h1.52
  text "X" at 346.417,122.495 h1.52
  text "BOTTOM" at 349.643,122.495 h1.52
  text "SILKSCREEN COLOR:" at 310.634,118.26 h1.52
  text "X" at 333.436,118.253 h1.52
  text "WHITE" at 336.663,118.253 h1.52
  text "OTHER" at 349.643,118.253 h1.52
  text "SOLDER RESIST COLOR:" at 309.364,113.935 h1.52
  text "GREEN" at 327.011,109.892 h1.52
  text "BLUE" at 342.023,109.892 h1.52
  text "OTHER" at 355.688,109.892 h1.52
  text "X" at 323.785,109.644 h1.52
  text "IMMERSION GOLD (ENIG)" at 332.371,105.103 h1.52
  text "ENEPIG" at 366.344,105.02 h1.52
  text "SURFACE FINISH:" at 305.421,104.994 h1.52
  text "X" at 327.622,104.994 h1.52
  text "IMM. TIN/SILVER OR EQUIV" at 313.792,101.007 h1.52
  text "OTHER" at 350.151,101.007 h1.52
  text "ARRAY/PANEL:" at 305.421,96.46 h1.52
  text "CUT AND TRIM PER MECH LAYER 1" at 332.371,96.351 h1.52
  text "N.C. ROUTE" at 332.371,92.498 h1.52
  text "X" at 349.617,92.498 h1.52
  text "V. SCORE" at 354.367,92.498 h1.52
  text "CERTIFICATION:" at 305.421,89.018 h1.52
  text "MATERIALS AND WORKMANSHIP FOR ALL PCBS" at 323.836,89.018 h1.52
  text "TO MEET OR EXCEED THE REQUIREMENTS OF:" at 323.836,86.529 h1.52
  text "X" at 314.349,83.061 h1.52
  text "ANSI IPC-A-600F CLASS ->" at 317.88,83.061 h1.52
  text "X" at 359.512,83.061 h1.52
  text "2" at 362.533,83.061 h1.52
  text "1" at 354.532,83.023 h1.52
  text "3" at 371.525,83.023 h1.52
  text "X" at 314.402,79.01 h1.52
  text "UL 94V-0" at 317.88,79.01 h1.52
  text "X" at 335.026,79.01 h1.52
  text "RoHS" at 338.505,79.01 h1.52
  text "OTHER" at 354.873,79.01 h1.52
  text "PER ORDER" at 364.958,79.01 h1.52
  text "ADDITIONAL REQUIREMENTS:" at 305.193,75.302 h1.52
  text "MICROSECTION:" at 307.092,72.381 h1.52
  text "YES" at 330.098,72.381 h1.52
  text "REQUIRED" at 352.208,68.542 h1.52
  text "NONE" at 340.486,68.469 h1.52
  text "X" at 348.982,68.469 h1.52
  text "PER ORDER" at 367.245,68.469 h1.52
  text "BARE BOARD ELEC. TEST:" at 307.092,68.342 h1.52
  text "MANUFACTURER'S UL:" at 307.092,64.354 h1.52
  text "METAL" at 349.422,64.373 h1.52
  text "X" at 358.953,64.364 h1.52
  text "SILK" at 362.419,64.373 h1.52
  text "RAIL" at 336.702,64.245 h1.52
M11 Gerber Information:
  lines w0.254: 10.16,16.607 177.8,16.607 ; 10.16,21.772 177.851,21.772 ; 10.16,26.937 10.16,11.443 111.887,11.443 177.851,11.443 177.851,26.937 10.173,26.937 10.173,11.443 50.19,11.443 ; 72.771,11.443 72.771,26.937 ; 104.953,21.772 104.953,26.937 ; 126.289,21.772 126.289,26.937 ; 142.088,11.278 142.088,16.43
  text "ALL ARTWORK VIEWED FROM TOP SIDE" at 11.773,23.58 h1.52
  text "BOARD #:" at 74.676,23.58 h1.52
  text ".PRJ_Number" at 88.532,23.58 h1.52
  text "REV:" at 109.982,23.58 h1.52
  text ".PCB_Rev" at 117.386,23.58 h1.52
  text "SVN REV:" at 131.267,23.58 h1.52
  text ".VersionControl_RevNumber" at 144.12,23.58 h1.52
  text "LAYER NAME =" at 11.773,18.428 h1.52
  text "PLOT NAME =" at 11.773,13.199 h1.52
  text ".plot_File_Name" at 32.233,13.199 h1.52
  text "GENERATED    :" at 74.727,13.199 h1.52
  text ".Print_Date" at 96.812,13.199 h1.52
  text ".Print_Time" at 115.329,13.199 h1.52
  text "TEXAS INSTRUMENTS" at 147.447,13.199 h1.52
M12 Stackup:
  lines w0.152: 305.105,221.59 369.875,221.59 ; 305.105,224.241 369.875,224.241 ; 303.581,209.271 ccw(c304.444,209.271) 304.444,208.407 370.535,208.407 ccw(c370.535,209.271) 371.399,209.271 371.399,227.203 ccw(c370.535,227.203) 370.535,228.067 304.444,228.067 ccw(c304.444,227.203) 303.581,227.203 303.581,209.271
  text "The Stackup Legend below this is static." at 311.34,232.118 h1.52
  text "If you change the stackup, update the Legend." at 311.594,229.832 h1.52
  text "Layer Stack Up Detail for: Ref_Design.PcbDoc" at 305.105,225.072 h1.45
  text "Layer" at 305.105,223.251 h0.61
  text "Gerber" at 327.858,223.251 h0.61
  text "Copper" at 342.172,223.251 h0.61
  text "Dielectric" at 357.481,223.251 h0.61
  text "Name" at 305.105,222.032 h0.61
  text "Document" at 327.858,222.032 h0.61
  text "Thickness" at 342.172,222.032 h0.61
  text "Material" at 357.481,222.032 h0.61
  text "Top Solder Mask" at 305.105,219.67 h0.86
  text "(.GTS)" at 327.858,219.67 h0.86
  text "Solder Resist" at 357.481,219.67 h0.86
  text ".Layer_Name" at 284.988,218.186 h1.52
  text "Top Layer" at 305.105,217.213 h0.86
  text "(.GTL)" at 327.858,217.213 h0.86
  text "1.4mil" at 342.172,217.213 h0.86
  text "FR-4" at 357.481,215.984 h0.86
  text "Bottom Layer" at 305.105,214.755 h0.86
  text "(.GBL)" at 327.858,214.755 h0.86
  text "1.4mil" at 342.172,214.755 h0.86
  text "Bottom Solder Mask" at 305.105,212.298 h0.86
  text "(.GBS)" at 327.858,212.298 h0.86
  text "Solder Resist" at 357.481,212.298 h0.86
M13 Component Bodies Top:
  text ".Layer_Name" at 157.226,138.786 h1.52
M14 Component Bodies Bottom:
  text ".Layer_Name" at 157.226,136.246 h1.52
M15 Courtyards Top:
  text ".Layer_Name" at 157.226,133.706 h1.52
M16 Courtyards Bottom:
  text ".Layer_Name" at 157.226,131.166 h1.52
Drill Drawing:
  text ".Layer_Name" at 157.226,105.766 h1.52

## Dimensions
144.018,143.358 to 151.917,158.471 on M2 Board Dimensions
27.584,143.358 to 20.218,169.037 on M2 Board Dimensions
124.587,61.646 to 151.917,58.649 on M2 Board Dimensions
20.218,58.649 to 47.879,60.96 on M2 Board Dimensions
132.588,143.358 to 144.018,143.358 on M2 Board Dimensions
27.584,143.358 to 39.014,143.358 on M2 Board Dimensions
17.577,29.807 to 42.977,29.807 on M2 Board Dimensions
74.752,72.492 to 98.12,72.492 on M2 Board Dimensions
98.12,97.13 to 98.12,72.492 on M2 Board Dimensions
98.628,71.984 to 124.587,61.646 on M2 Board Dimensions
47.879,60.96 to 74.193,71.984 on M2 Board Dimensions
47.879,60.96 to 124.587,61.646 on M2 Board Dimensions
